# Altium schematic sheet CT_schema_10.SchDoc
size 278 x 170 mm
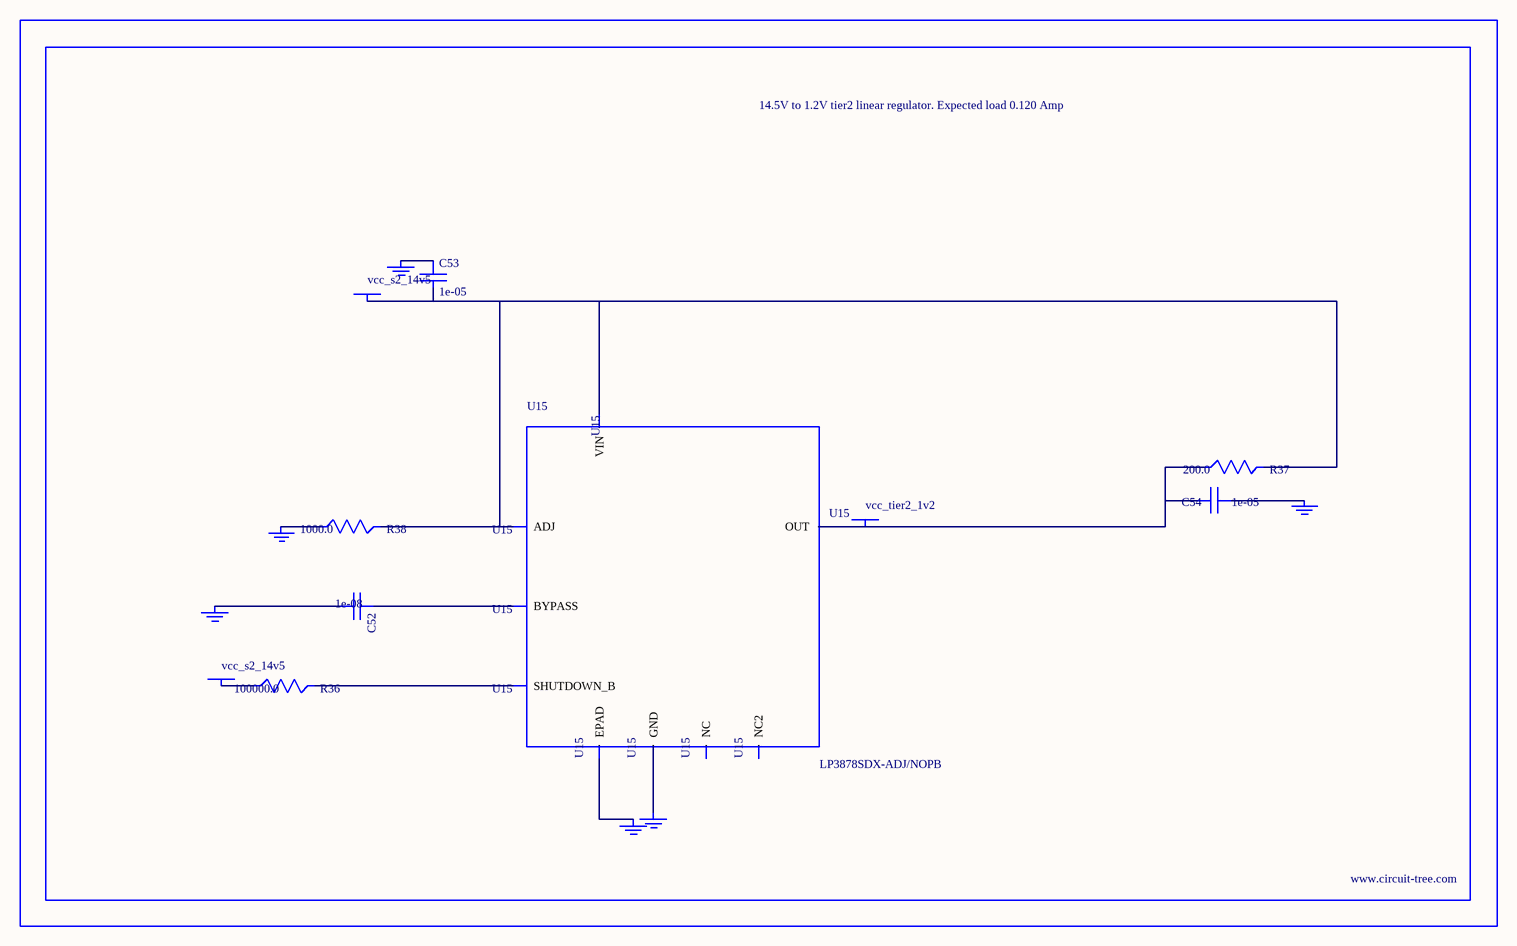
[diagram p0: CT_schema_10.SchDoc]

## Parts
BORDER9  (no value)
C52  1e-08  [C0402]
C53  1e-05  [C1210]
C54  1e-05  [C0805]
GND_INSTANCE_9_0  (no value)
GND_INSTANCE_9_1  (no value)
GND_INSTANCE_9_2  (no value)
GND_INSTANCE_9_3  (no value)
GND_INSTANCE_9_4  (no value)
GND_INSTANCE_9_5  (no value)
POWER_INSTANCE_9_0  vcc_s2_14v5
POWER_INSTANCE_9_1  vcc_s2_14v5
POWER_INSTANCE_9_2  vcc_tier2_1v2
R36  100000.0  [R0603]
R37  200.0  [R0603]
R38  1000.0  [R0603]
U15  LP3878SDX-ADJ/NOPB  [WSON-8]

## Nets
NetC52_1: C52.1 U15.1(BYPASS)
NetC52_2: C52.2 GND_INSTANCE_9_0.0(GND)
NetC53_1: C53.1 GND_INSTANCE_9_1.0(GND)
NetC53_2: C53.2 POWER_INSTANCE_9_0.0(PWR) R37.2 R38.2 U15.4(VIN) U15.6(ADJ)
NetC54_1: C54.1 GND_INSTANCE_9_2.0(GND)
NetC54_2: C54.2 POWER_INSTANCE_9_2.0(PWR) R37.1 U15.5(OUT)
NetGND_INSTANCE_9_3_0: GND_INSTANCE_9_3.0(GND) R38.1
NetGND_INSTANCE_9_4_0: GND_INSTANCE_9_4.0(GND) U15.PAD(EPAD)
NetGND_INSTANCE_9_5_0: GND_INSTANCE_9_5.0(GND) U15.3(GND)
NetPOWER_INSTANCE_9_1_0: POWER_INSTANCE_9_1.0(PWR) R36.1
NetR36_2: R36.2 U15.8(SHUTDOWN_B)

Not connected (* = marked no-connect by the designer): U15 2(NC) 7(NC2)

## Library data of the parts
BORDER9 = BORDER_PAGE9
C52 = C0402C103K3RAC
C53 = C1210C106K5PACTU
C54 = GRM219R60J106ME19D
GND_INSTANCE_9_0-GND_INSTANCE_9_5 = GND
POWER_INSTANCE_9_0-POWER_INSTANCE_9_2 = PWR
R36 = RC0603JR-07100KL
R37 = RC0603JR-07200RL
R38 = RC0603JR-071KL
